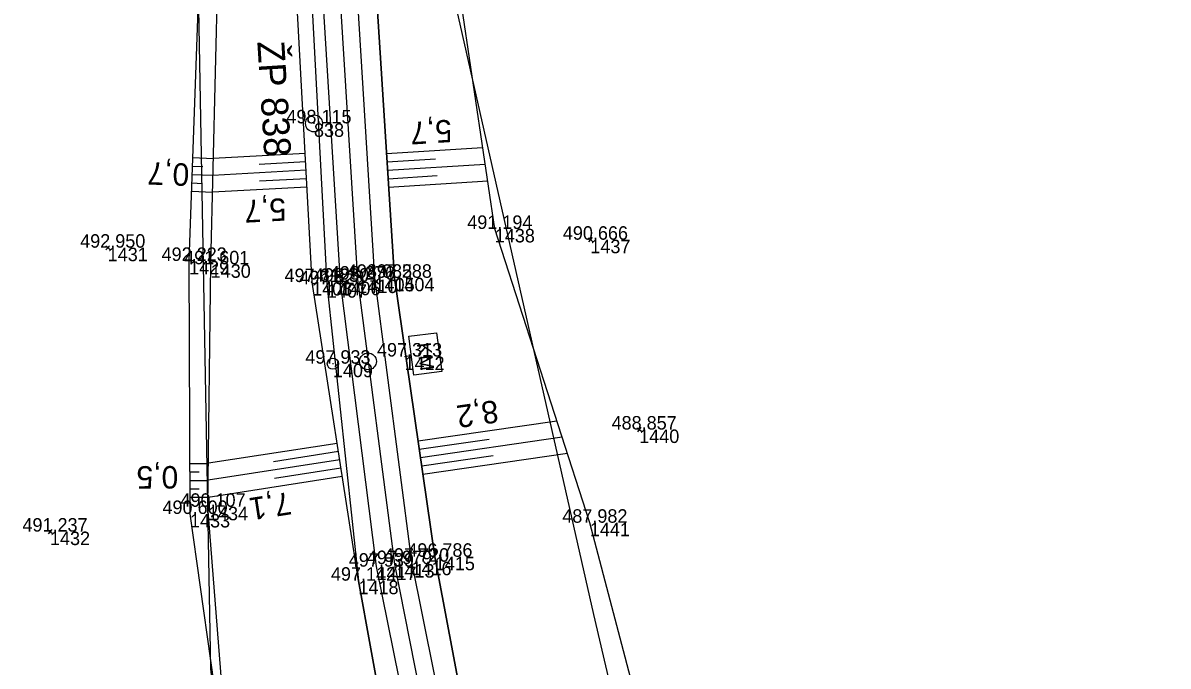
# Model space of a CAD drawing. Extents: x -1234191 to 23050, y -1290331 to -741191.
# Drawn here: x -865316.4 to -865214.4, y -1106898.4 to -1106841.1 of the extents above; entities that cross this region are included whole.
import ezdxf

# ---------------------------------------------------------------- set-up
doc = ezdxf.new("R2010")
doc.units = 0
for name, color, linetype in [('Vrstva 1', 7, 'Continuous'), ('Vrstva 4', 7, 'Continuous'), ('Vrstva 48', 7, 'Continuous'), ('Vrstva 49', 7, 'Continuous'), ('Vrstva 53', 7, 'Continuous'), ('Vrstva 60', 7, 'Continuous'), ('Vrstva 61', 7, 'Continuous'), ('Vrstva 63', 7, 'Continuous'), ('Vrstva 7', 7, 'Continuous')]:
    doc.layers.add(name, color=color, linetype=linetype)

msp = doc.modelspace()

# ---------------------------------------------------------------- linework, layer by layer
at = {"layer": 'Vrstva 1'}
msp.add_lwpolyline([(-865261.7, -1106689.97), (-865270.22, -1106713.53), (-865277.08, -1106737.46), (-865282.34, -1106761.77), (-865285.99, -1106786.57), (-865287.95, -1106811.51), (-865288.19, -1106838.09), (-865286.59, -1106863.96), (-865283.29, -1106889.29), (-865278.34, -1106914.26), (-865271.61, -1106938.96), (-865263.39, -1106962.53), (-865253.95, -1106984.99), (-865244.3, -1107004.68)], dxfattribs=at)
at = {"layer": 'Vrstva 4'}
for points in [[(-865264.95, -1106688.91), (-865272.84, -1106712.23), (-865280.58, -1106736.8), (-865286.43, -1106761.05), (-865289.73, -1106786.08), (-865291.5, -1106811.5), (-865290.69, -1106838.14), (-865289.3, -1106864.37), (-865286.49, -1106890.77), (-865282.09, -1106915), (-865275.46, -1106934.87)], [(-865272.5, -1106944.55), (-865272.57, -1106944.57), (-865272.57, -1106944.57), (-865275.54, -1106934.9), (-865275.54, -1106934.9), (-865275.46, -1106934.87), (-865279.82, -1106914.59), (-865284.89, -1106889.52), (-865288.1, -1106864.15), (-865289.7, -1106838.09), (-865289.52, -1106811.54), (-865287.32, -1106786.54), (-865283.65, -1106761.54), (-865278.6, -1106737.21), (-865271.61, -1106713.21), (-865263.16, -1106689.66)], [(-865260.38, -1106690.75), (-865268.8, -1106714.12), (-865275.66, -1106737.95), (-865280.85, -1106762.05), (-865284.5, -1106786.89), (-865286.48, -1106811.61), (-865286.75, -1106837.72), (-865286.75, -1106836.31), (-865285.06, -1106863.8), (-865281.77, -1106889.08), (-865276.76, -1106914.02), (-865271.55, -1106933.15), (-865270.95, -1106932.97), (-865275.2, -1106912.49), (-865279.69, -1106888.64), (-865283.29, -1106863.8), (-865284.94, -1106837.69), (-865285.02, -1106811.81), (-865282.87, -1106786.88), (-865279.2, -1106762.42), (-865273.95, -1106738.28), (-865267.2, -1106714.69), (-865258.68, -1106691.02)]]:
    msp.add_lwpolyline(points, dxfattribs=at)
at = {"layer": 'Vrstva 48'}
for p, q in [((-865283.99, -1106852.73), (-865275.43, -1106852.19)), ((-865301.23, -1106853.1), (-865299.42, -1106853.17)), ((-865291.24, -1106852.73), (-865299.42, -1106853.17)), ((-865291.2, -1106853.48), (-865295.32, -1106853.7)), ((-865283.94, -1106853.48), (-865279.63, -1106853.21)), ((-865301.26, -1106853.85), (-865300.35, -1106853.89)), ((-865291.16, -1106854.23), (-865299.45, -1106854.68)), ((-865283.9, -1106854.23), (-865275.2, -1106853.68)), ((-865301.32, -1106855.35), (-865300.39, -1106855.39)), ((-865301.29, -1106854.6), (-865299.45, -1106854.67)), ((-865291.12, -1106854.98), (-865295.29, -1106855.2)), ((-865283.85, -1106854.98), (-865279.47, -1106854.7)), ((-865283.8, -1106855.73), (-865274.98, -1106855.17)), ((-865301.34, -1106856.1), (-865299.49, -1106856.17)), ((-865291.08, -1106855.73), (-865299.49, -1106856.18)), ((-865281.18, -1106878.32), (-865268.83, -1106876.53)), ((-865280.97, -1106879.8), (-865268.36, -1106877.97)), ((-865288.39, -1106878.54), (-865299.84, -1106880.31)), ((-865281.08, -1106879.06), (-865274.84, -1106878.16)), ((-865288.16, -1106880.02), (-865299.86, -1106881.83)), ((-865288.28, -1106879.28), (-865294.06, -1106880.18)), ((-865280.86, -1106880.55), (-865274.49, -1106879.62)), ((-865280.75, -1106881.29), (-865267.89, -1106879.42)), ((-865301.5, -1106880.34), (-865299.84, -1106880.34)), ((-865288.05, -1106880.76), (-865293.96, -1106881.68)), ((-865301.5, -1106881.09), (-865300.68, -1106881.09)), ((-865301.5, -1106881.84), (-865299.86, -1106881.84)), ((-865287.93, -1106881.5), (-865299.88, -1106883.35)), ((-865301.49, -1106882.59), (-865300.68, -1106882.59)), ((-865301.49, -1106883.34), (-865299.88, -1106883.34))]:
    msp.add_line(p, q, dxfattribs=at)
at = {"layer": 'Vrstva 49'}
for p, q in [((-865266.02, -1106860.24), (-865265.65, -1106860.57)), ((-865265.67, -1106860.22), (-865266, -1106860.6)), ((-865309, -1106860.96), (-865308.63, -1106861.29)), ((-865308.65, -1106860.94), (-865308.98, -1106861.31)), ((-865261.69, -1106877.16), (-865261.3, -1106877.46)), ((-865261.34, -1106877.11), (-865261.65, -1106877.51)), ((-865314.15, -1106886.25), (-865313.76, -1106886.55)), ((-865313.8, -1106886.2), (-865314.11, -1106886.6))]:
    msp.add_line(p, q, dxfattribs=at)
for points in [[(-865297.8, -1106910.95), (-865301.49, -1106884.83), (-865301.57, -1106862.3), (-865300.66, -1106837.39), (-865298.37, -1106810.16), (-865294.53, -1106785.6), (-865287.98, -1106760.27), (-865282.97, -1106736.07), (-865277.68, -1106710.81), (-865271.22, -1106686.12), (-865260.83, -1106663.97), (-865250.75, -1106645.73), (-865240.74, -1106625.96), (-865230.04, -1106606.79), (-865221.82, -1106591.38), (-865215.71, -1106580.01), (-865206.84, -1106567.4), (-865200.8, -1106554.97), (-865189.9, -1106532.43), (-865180.71, -1106509.04), (-865172.12, -1106485.47)], [(-865297.8, -1106910.95), (-865299.89, -1106884.19), (-865299.65, -1106862.6), (-865299.01, -1106836.91), (-865295.93, -1106809.86), (-865292.44, -1106784.8), (-865286.43, -1106761.05), (-865280.58, -1106736.8), (-865273.87, -1106712.18), (-865265.74, -1106688.57)], [(-865264.56, -1106716.17), (-865271.09, -1106739.15), (-865276.67, -1106762.55), (-865281.81, -1106787.37), (-865284.19, -1106811.86), (-865284.94, -1106837.69), (-865283.29, -1106863.8), (-865279.69, -1106888.64), (-865275.2, -1106912.49), (-865270.95, -1106932.97), (-865270.71, -1106933.73)], [(-865259.72, -1106924.76), (-865259.45, -1106925.3), (-865261.52, -1106902.22), (-865265.89, -1106885.61), (-865274.35, -1106859.45), (-865277.73, -1106836.63), (-865279.95, -1106811.78), (-865277.7, -1106789.14), (-865275.34, -1106763.49), (-865269.2, -1106740.29), (-865264.56, -1106716.17)], [(-865275.34, -1106935.27), (-865275.46, -1106934.87), (-865282.09, -1106915), (-865286.49, -1106890.77), (-865290.62, -1106864.18), (-865292.07, -1106837.43), (-865291.5, -1106811.5), (-865289.73, -1106786.08), (-865286.43, -1106761.05)]]:
    msp.add_lwpolyline(points, dxfattribs=at)
at = {"layer": 'Vrstva 53'}
for points in [[(-865238.82, -1106657.44), (-865256.95, -1106698.52), (-865276.74, -1106765.17), (-865279.74, -1106831.09), (-865265.56, -1106893.79), (-865256.25, -1106933.64), (-865247.14, -1106989.91), (-865222.8, -1107004.87), (-865201.31, -1107030.96), (-865196.45, -1107073.73), (-865163.46, -1107128.75), (-865136.19, -1107176.03), (-865109.59, -1107240.55), (-865092.98, -1107247.14), (-865086.64, -1107264.13), (-865095.13, -1107273.62), (-865092.53, -1107296.42)], [(-865031.84, -1107728.7), (-865056.26, -1107614.01), (-865082.13, -1107527.34), (-865093.98, -1107443.05), (-865102.44, -1107349.87), (-865111.7, -1107288.18), (-865115.78, -1107279.62), (-865126.55, -1107239.39), (-865152.22, -1107173.12), (-865183.78, -1107119.15), (-865210.51, -1107089.36), (-865241.35, -1107035.57), (-865260.95, -1106990.6), (-865287.43, -1106945.67), (-865298.94, -1106904.64), (-865299.65, -1106898.63), (-865300.82, -1106833.27), (-865292.28, -1106759.44), (-865281, -1106690.92)]]:
    msp.add_lwpolyline(points, dxfattribs=at)
at = {"layer": 'Vrstva 60'}
for p, q in [((-865290.45, -1106850.05), (-865290.45, -1106850.05)), ((-865274.35, -1106859.45), (-865274.35, -1106859.45)), ((-865265.84, -1106860.41), (-865265.84, -1106860.41)), ((-865308.82, -1106861.12), (-865308.82, -1106861.12)), ((-865301.57, -1106862.3), (-865301.57, -1106862.3)), ((-865299.65, -1106862.6), (-865299.65, -1106862.6)), ((-865290.62, -1106864.18), (-865290.62, -1106864.18)), ((-865289.3, -1106864.37), (-865289.3, -1106864.37)), ((-865288.1, -1106864.15), (-865288.1, -1106864.15)), ((-865286.59, -1106863.96), (-865286.59, -1106863.96)), ((-865285.06, -1106863.8), (-865285.06, -1106863.8)), ((-865283.29, -1106863.8), (-865283.29, -1106863.8)), ((-865282.39, -1106870.81), (-865282.39, -1106870.81)), ((-865288.77, -1106871.45), (-865288.77, -1106871.45)), ((-865261.49, -1106877.31), (-865261.49, -1106877.31)), ((-865301.49, -1106884.83), (-865301.49, -1106884.83)), ((-865299.89, -1106884.19), (-865299.89, -1106884.19)), ((-865265.89, -1106885.61), (-865265.89, -1106885.61)), ((-865313.96, -1106886.4), (-865313.96, -1106886.4)), ((-865281.77, -1106889.08), (-865281.77, -1106889.08)), ((-865279.69, -1106888.64), (-865279.69, -1106888.64)), ((-865284.89, -1106889.52), (-865284.89, -1106889.52)), ((-865283.29, -1106889.29), (-865283.29, -1106889.29)), ((-865286.49, -1106890.77), (-865286.49, -1106890.77))]:
    msp.add_line(p, q, dxfattribs=at)
at = {"layer": 'Vrstva 63'}
msp.add_line((-865290.46, -1106850), (-865290.45, -1106850.1), dxfattribs=at)
msp.add_circle((-865290.45, -1106850.05), 0.756, dxfattribs=at)
at = {"layer": 'Vrstva 7'}
for p, q in [((-865282.39, -1106870.81), (-865281.77, -1106870.73)), ((-865288.78, -1106871.4), (-865288.77, -1106871.5))]:
    msp.add_line(p, q, dxfattribs=at)
msp.add_lwpolyline([(-865282, -1106869.01), (-865279.53, -1106868.69), (-865279.08, -1106872.14), (-865281.55, -1106872.47)], close=True, dxfattribs=at)
for centre, radius in [((-865285.64, -1106871.24), 0.75), ((-865288.77, -1106871.45), 0.5)]:
    msp.add_circle(centre, radius, dxfattribs=at)

# ---------------------------------------------------------------- texts
at = {"layer": 'Vrstva 48'}
for s, rotation, p in [('5,7', 183.6002, (-865278.23, -1106849.71)), ('0,7', 177.9164, (-865301.52, -1106853.63)), ('5,7', 183.1073, (-865292.99, -1106856.7)), ('8,2', 188.265, (-865274.19, -1106874.67)), ('0,5', 180.206, (-865302.54, -1106880.56)), ('7,1', 188.8119, (-865292.65, -1106882.86))]:
    msp.add_text(s, height=2, rotation=rotation, dxfattribs=at).set_placement(p)
at = {"layer": 'Vrstva 60'}
for s, p in [('838', (-865290.45, -1106851.25)), ('1438', (-865274.35, -1106860.65)), ('1437', (-865265.84, -1106861.61)), ('1431', (-865308.82, -1106862.32)), ('1429', (-865301.57, -1106863.5)), ('1430', (-865299.65, -1106863.8)), ('1408', (-865290.62, -1106865.38)), ('1407', (-865289.3, -1106865.57)), ('1406', (-865288.1, -1106865.35)), ('1410', (-865286.59, -1106865.16)), ('1405', (-865285.06, -1106865.01)), ('1404', (-865283.29, -1106865)), ('1412', (-865282.39, -1106872.02)), ('1409', (-865288.77, -1106872.65)), ('1440', (-865261.49, -1106878.51)), ('1433', (-865301.49, -1106886.03)), ('1434', (-865299.89, -1106885.39)), ('1441', (-865265.89, -1106886.81)), ('1432', (-865313.96, -1106887.6)), ('1416', (-865281.77, -1106890.28)), ('1415', (-865279.69, -1106889.84)), ('1417', (-865284.89, -1106890.72)), ('1413', (-865283.29, -1106890.49)), ('1418', (-865286.49, -1106891.97))]:
    msp.add_text(s, height=1.2, dxfattribs=at).set_placement(p)
at = {"layer": 'Vrstva 61'}
for s, p in [('498.115', (-865292.91, -1106850.05)), ('491.194', (-865276.8, -1106859.45)), ('490.666', (-865268.29, -1106860.41)), ('492.950', (-865311.27, -1106861.12)), ('492.223', (-865304.02, -1106862.3)), ('491.601', (-865302.01, -1106862.6)), ('498.085', (-865287.52, -1106863.8)), ('497.288', (-865285.75, -1106863.8)), ('497.612', (-865293.07, -1106864.18)), ('497.823', (-865291.75, -1106864.37)), ('498.301', (-865290.46, -1106864.15)), ('498.276', (-865289.04, -1106863.96)), ('497.313', (-865284.84, -1106870.81)), ('497.933', (-865291.22, -1106871.45)), ('488.857', (-865263.95, -1106877.31)), ('490.107', (-865302.34, -1106884.19)), ('490.600', (-865303.94, -1106884.83)), ('487.982', (-865268.34, -1106885.61)), ('491.237', (-865316.41, -1106886.4)), ('497.979', (-865285.74, -1106889.29)), ('497.720', (-865284.22, -1106889.08)), ('496.786', (-865282.14, -1106888.64)), ('497.939', (-865287.35, -1106889.52)), ('497.142', (-865288.94, -1106890.77))]:
    msp.add_text(s, height=1.2, dxfattribs=at).set_placement(p)
at = {"layer": 'Vrstva 63'}
msp.add_text('ŽP 838', height=2.4, rotation=273.5423, dxfattribs=at).set_placement((-865295.5, -1106842.78))
at = {"layer": 'Vrstva 7'}
msp.add_text('KM', height=1.247, rotation=277.4288, dxfattribs=at).set_placement((-865281.29, -1106869.65))

doc.saveas('drawing.dxf')
